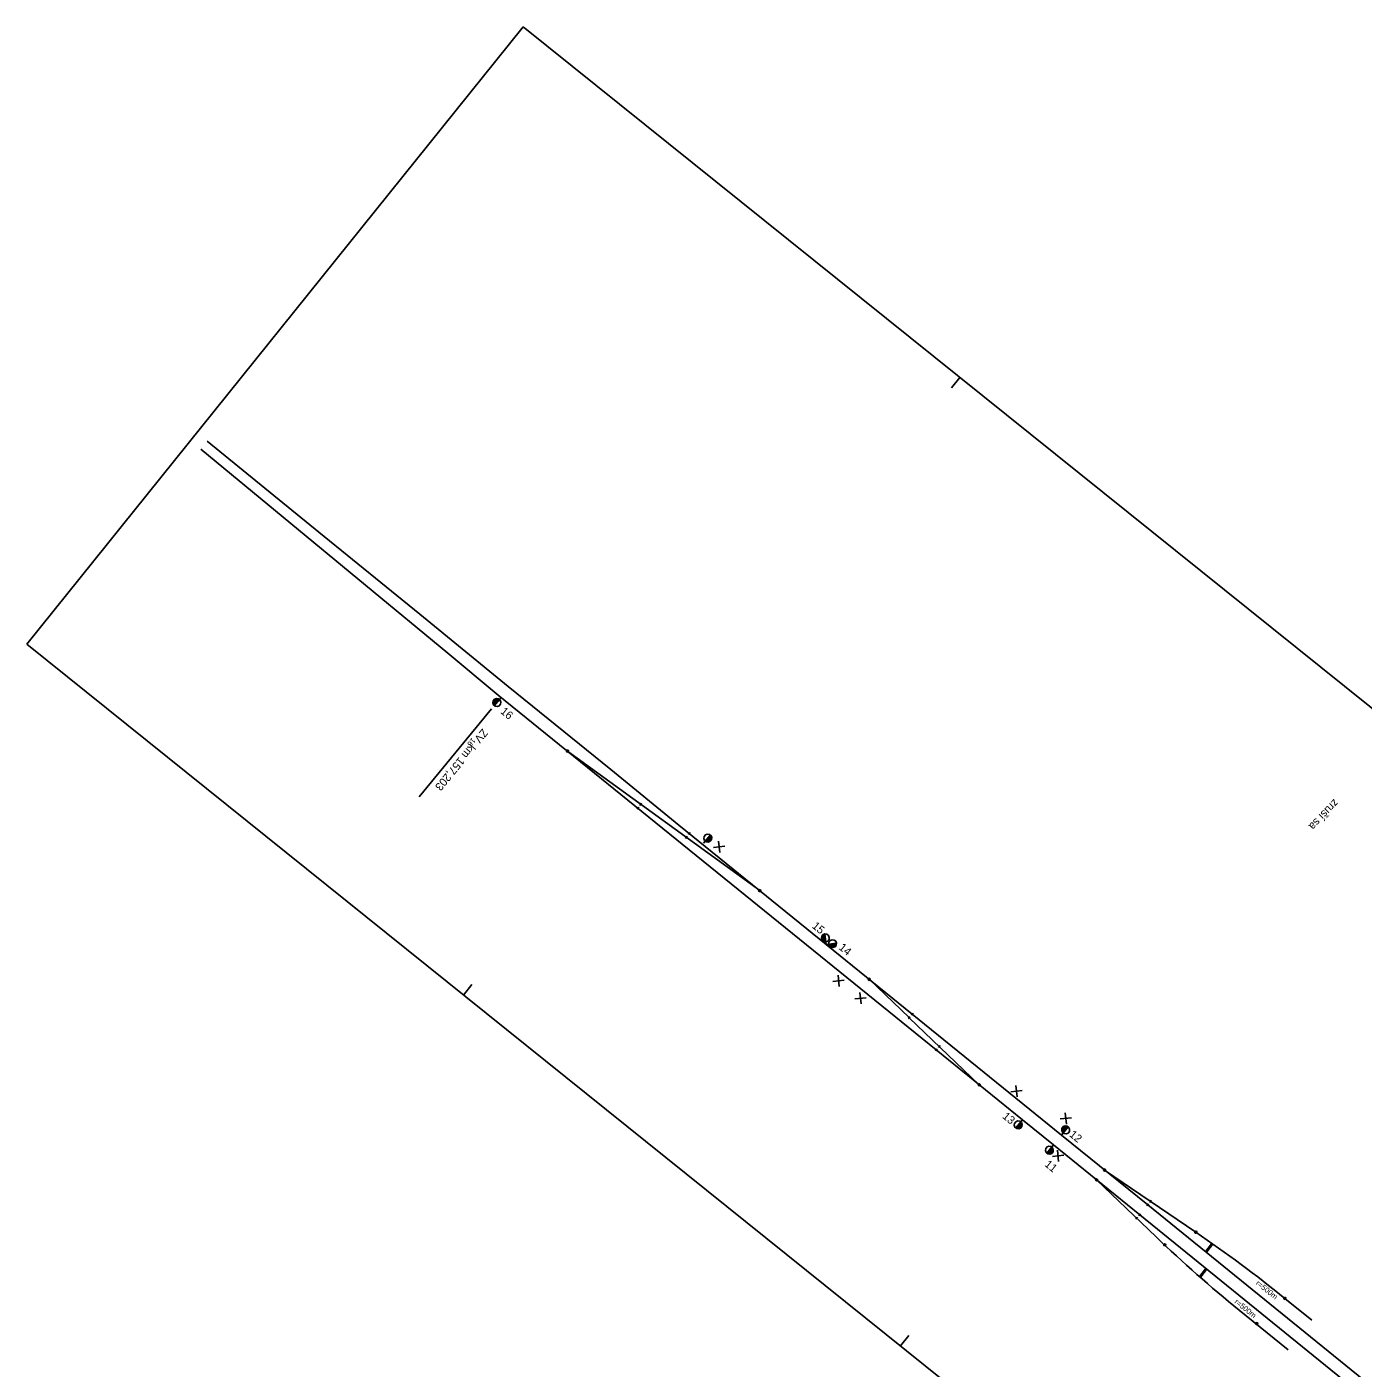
# Model space of a CAD drawing. Extents: x -486838 to -485015, y -1312876 to -1311330.
# Drawn here: x -486838 to -486337, y -1311833 to -1311330 of the extents above; entities that cross this region are included whole.
import ezdxf

# ---------------------------------------------------------------- set-up
doc = ezdxf.new("R2010")
doc.units = 0
for name, color, linetype in [('kolaj s', 7, 'Continuous'), ('Level 61', 7, 'Continuous'), ('popis 25', 7, 'Continuous'), ('popis 35', 7, 'Continuous'), ('stavby', 7, 'Continuous')]:
    doc.layers.add(name, color=color, linetype=linetype)

msp = doc.modelspace()

# ---------------------------------------------------------------- linework, layer by layer
at = {"layer": 'kolaj s'}
for p, q in [((-486770.47, -1311484.97), (-486728.55, -1311519.09)), ((-486680.25, -1311564.37), (-486772.84, -1311487.92)), ((-486728.55, -1311519.09), (-486690.72, -1311549.81)), ((-486690.72, -1311549.81), (-486657.65, -1311576.88)), ((-486661.35, -1311580.12), (-486680.25, -1311564.37)), ((-486657.65, -1311576.88), (-486619.12, -1311608)), ((-486661.35, -1311580.12), (-486497.17, -1311713.19)), ((-486635.41, -1311601.14), (-486635.41, -1311601.14)), ((-486635.41, -1311601.14), (-486563.34, -1311653.44)), ((-486619.12, -1311608), (-486593.64, -1311628.92)), ((-486609.3, -1311622.93), (-486608.68, -1311622.15)), ((-486608.99, -1311622.54), (-486608.99, -1311622.54)), ((-486608.22, -1311621.5), (-486607.59, -1311620.72)), ((-486607.91, -1311621.11), (-486607.91, -1311621.11)), ((-486593.64, -1311628.92), (-486538.46, -1311673.61)), ((-486590.04, -1311632.43), (-486589.41, -1311631.65)), ((-486589.72, -1311632.04), (-486589.72, -1311632.04)), ((-486584.38, -1311635.67), (-486581.89, -1311632.6)), ((-486591.18, -1311633.86), (-486590.55, -1311633.08)), ((-486590.87, -1311633.47), (-486590.87, -1311633.47)), ((-486584.38, -1311635.67), (-486584.38, -1311635.67)), ((-486563.34, -1311653.44), (-486563.34, -1311653.44)), ((-486538.46, -1311673.61), (-486506.15, -1311699.8)), ((-486522.3, -1311686.7), (-486522.3, -1311686.7)), ((-486522.3, -1311686.7), (-486507.29, -1311701.09)), ((-486506.94, -1311700.73), (-486507.64, -1311701.46)), ((-486507.29, -1311701.09), (-486507.29, -1311701.09)), ((-486481.02, -1311726.28), (-486507.29, -1311701.1)), ((-486505.83, -1311699.41), (-486506.46, -1311700.19)), ((-486506.15, -1311699.8), (-486506.15, -1311699.8)), ((-486506.15, -1311699.8), (-486450.22, -1311745.13)), ((-486497.49, -1311713.57), (-486496.86, -1311712.8)), ((-486464.86, -1311739.38), (-486497.17, -1311713.19)), ((-486497.17, -1311713.19), (-486497.17, -1311713.19)), ((-486496.38, -1311712.25), (-486495.68, -1311711.53)), ((-486496.03, -1311711.89), (-486496.03, -1311711.89)), ((-486481.02, -1311726.28), (-486481.02, -1311726.28)), ((-486464.86, -1311739.38), (-486453.21, -1311748.82)), ((-486450.22, -1311745.13), (-486417.9, -1311771.32)), ((-486453.21, -1311748.82), (-486420.89, -1311775.01)), ((-486434.06, -1311758.23), (-486434.06, -1311758.23)), ((-486434.06, -1311758.23), (-486399.86, -1311781.52)), ((-486437.05, -1311761.92), (-486437.05, -1311761.92)), ((-486437.05, -1311761.92), (-486414.73, -1311783.31)), ((-486417.59, -1311770.93), (-486418.22, -1311771.71)), ((-486417.9, -1311771.32), (-486114.2, -1312017.47)), ((-486417.9, -1311771.32), (-486417.9, -1311771.32)), ((-486416.59, -1311769.52), (-486417.15, -1311770.35)), ((-486416.87, -1311769.93), (-486416.87, -1311769.93)), ((-486421.69, -1311775.94), (-486422.38, -1311776.67)), ((-486422.04, -1311776.31), (-486422.04, -1311776.31)), ((-486420.58, -1311774.62), (-486421.21, -1311775.4)), ((-486420.89, -1311775.01), (-486117.19, -1312021.16)), ((-486420.89, -1311775.01), (-486420.89, -1311775.01)), ((-486399.86, -1311781.52), (-486399.86, -1311781.52)), ((-486411.54, -1311786.26), (-486411.54, -1311786.26)), ((-486366.48, -1311806.35), (-486366.48, -1311806.35)), ((-486366.48, -1311806.35), (-486356.38, -1311814.54)), ((-486383.59, -1311810.77), (-486365.28, -1311825.61)), ((-486377.05, -1311815.79), (-486377.05, -1311815.79))]:
    msp.add_line(p, q, dxfattribs=at)
for points in [[(-486635.16, -1311600.83), (-486635.02, -1311601.2), (-486635.27, -1311601.51), (-486635.66, -1311601.46), (-486635.81, -1311601.08), (-486635.56, -1311600.77), (-486635.16, -1311600.83)], [(-486581.59, -1311632.86), (-486582.21, -1311632.36), (-486582.97, -1311632.24), (-486583.69, -1311632.52), (-486584.19, -1311633.14), (-486584.3, -1311633.89), (-486584, -1311634.64), (-486583.42, -1311635.11), (-486582.65, -1311635.23), (-486581.93, -1311634.96), (-486581.43, -1311634.34), (-486581.32, -1311633.58), (-486581.59, -1311632.86), (-486581.55, -1311633.21), (-486581.94, -1311632.9), (-486582.13, -1311633.13), (-486581.47, -1311633.66), (-486581.5, -1311634.03), (-486582.32, -1311633.37), (-486582.5, -1311633.6), (-486581.61, -1311634.32), (-486581.8, -1311634.55), (-486582.7, -1311633.83), (-486582.88, -1311634.07), (-486581.99, -1311634.79), (-486582.29, -1311634.93), (-486583.07, -1311634.3), (-486583.26, -1311634.53), (-486582.6, -1311635.06), (-486583.1, -1311635.05), (-486583.45, -1311634.76)], [(-486563.09, -1311653.13), (-486562.95, -1311653.5), (-486563.2, -1311653.81), (-486563.59, -1311653.75), (-486563.74, -1311653.38), (-486563.49, -1311653.07), (-486563.09, -1311653.13)], [(-486521.99, -1311686.96), (-486522.37, -1311687.1), (-486522.68, -1311686.85), (-486522.61, -1311686.45), (-486522.24, -1311686.31), (-486521.93, -1311686.56), (-486521.99, -1311686.96)], [(-486481.33, -1311726.03), (-486480.96, -1311725.89), (-486480.65, -1311726.14), (-486480.71, -1311726.53), (-486481.08, -1311726.67), (-486481.39, -1311726.42), (-486481.33, -1311726.03)], [(-486433.75, -1311758.48), (-486434.12, -1311758.62), (-486434.43, -1311758.37), (-486434.37, -1311757.97), (-486434, -1311757.83), (-486433.69, -1311758.08), (-486433.75, -1311758.48)], [(-486436.74, -1311762.17), (-486437.11, -1311762.31), (-486437.42, -1311762.06), (-486437.36, -1311761.66), (-486436.99, -1311761.52), (-486436.68, -1311761.77), (-486436.74, -1311762.17)], [(-486399.64, -1311781.19), (-486399.47, -1311781.55), (-486399.69, -1311781.88), (-486400.09, -1311781.85), (-486400.26, -1311781.49), (-486400.04, -1311781.16), (-486399.64, -1311781.19)], [(-486411.26, -1311785.97), (-486411.15, -1311786.35), (-486411.42, -1311786.64), (-486411.81, -1311786.55), (-486411.92, -1311786.16), (-486411.65, -1311785.87), (-486411.26, -1311785.97)], [(-486366.73, -1311806.66), (-486366.87, -1311806.29), (-486366.62, -1311805.98), (-486366.23, -1311806.04), (-486366.08, -1311806.42), (-486366.33, -1311806.73), (-486366.73, -1311806.66)], [(-486377.3, -1311816.1), (-486377.44, -1311815.73), (-486377.19, -1311815.42), (-486376.79, -1311815.48), (-486376.65, -1311815.86), (-486376.9, -1311816.17), (-486377.3, -1311816.1)]]:
    msp.add_lwpolyline(points, dxfattribs=at)
for centre, start, end in [((-486068.73, -1311422.36), 226.2117, 230.9705), ((-486681.33, -1312194.77), 50.9712, 55.7405)]:
    msp.add_arc(centre, 500, start, end, dxfattribs=at)
at = {"layer": 'Level 61'}
for p, q in [((-486652.04, -1311329.55), (-486838.03, -1311561.1)), ((-486652.04, -1311329.55), (-486160.87, -1311724.08)), ((-486488.32, -1311461.06), (-486491.45, -1311464.96)), ((-486346.87, -1311955.63), (-486838.03, -1311561.1)), ((-486671.18, -1311688.71), (-486674.31, -1311692.61)), ((-486507.46, -1311820.22), (-486510.59, -1311824.12))]:
    msp.add_line(p, q, dxfattribs=at)
at = {"layer": 'popis 25'}
for p, q in [((-486396.13, -1311788.65), (-486393.94, -1311785.91)), ((-486395.77, -1311788.93), (-486393.59, -1311786.2)), ((-486398.39, -1311797.98), (-486396.2, -1311795.25)), ((-486398.03, -1311798.27), (-486395.85, -1311795.53))]:
    msp.add_line(p, q, dxfattribs=at)
at = {"layer": 'popis 35'}
for p, q in [((-486660.29, -1311580.98), (-486662.77, -1311584.06)), ((-486660.29, -1311580.98), (-486660.29, -1311580.98)), ((-486663.84, -1311585.3), (-486690.93, -1311618.31)), ((-486576.39, -1311636.82), (-486580.64, -1311637.28)), ((-486578.28, -1311639.18), (-486578.74, -1311634.93)), ((-486538.46, -1311673.61), (-486538.46, -1311673.61)), ((-486531.62, -1311687.05), (-486535.87, -1311687.52)), ((-486533.51, -1311689.41), (-486533.97, -1311685.16)), ((-486525.35, -1311695.96), (-486525.82, -1311691.71)), ((-486523.46, -1311693.61), (-486527.71, -1311694.07)), ((-486464.95, -1311728.41), (-486469.2, -1311728.87)), ((-486466.85, -1311730.77), (-486467.31, -1311726.52)), ((-486446.44, -1311738.62), (-486450.69, -1311739.08)), ((-486448.34, -1311740.97), (-486448.8, -1311736.72)), ((-486464.86, -1311739.38), (-486467.33, -1311742.46)), ((-486464.86, -1311739.38), (-486464.86, -1311739.38)), ((-486450.22, -1311745.13), (-486447.74, -1311742.05)), ((-486450.22, -1311745.13), (-486450.22, -1311745.13)), ((-486453.21, -1311748.82), (-486455.68, -1311751.9)), ((-486449.39, -1311752.65), (-486453.64, -1311753.12)), ((-486453.21, -1311748.82), (-486453.21, -1311748.82)), ((-486451.29, -1311755.01), (-486451.75, -1311750.76))]:
    msp.add_line(p, q, dxfattribs=at)
for points in [[(-486663.08, -1311583.81), (-486662.45, -1311584.31), (-486661.7, -1311584.42), (-486660.98, -1311584.15), (-486660.48, -1311583.52), (-486660.37, -1311582.77), (-486660.64, -1311582.05), (-486661.26, -1311581.55), (-486662.02, -1311581.44), (-486662.74, -1311581.71), (-486663.24, -1311582.33), (-486663.35, -1311583.09), (-486663.08, -1311583.81), (-486663.12, -1311583.46), (-486662.73, -1311583.77), (-486662.54, -1311583.54), (-486663.2, -1311583), (-486663.13, -1311582.68), (-486662.35, -1311583.3), (-486662.16, -1311583.07), (-486663.06, -1311582.35), (-486662.87, -1311582.11), (-486661.98, -1311582.83), (-486661.79, -1311582.6), (-486662.68, -1311581.88), (-486662.38, -1311581.74), (-486661.6, -1311582.37), (-486661.41, -1311582.13), (-486662.07, -1311581.6), (-486661.57, -1311581.62), (-486661.22, -1311581.9)], [(-486538.57, -1311672.64), (-486537.84, -1311672.36), (-486537.36, -1311671.75), (-486537.24, -1311670.99), (-486537.52, -1311670.26), (-486538.12, -1311669.78), (-486538.89, -1311669.66), (-486539.61, -1311669.94), (-486540.1, -1311670.54), (-486540.22, -1311671.31), (-486539.94, -1311672.03), (-486539.33, -1311672.52), (-486538.57, -1311672.64), (-486538.75, -1311672.29), (-486539.38, -1311672.36), (-486539.69, -1311672.11), (-486538.85, -1311672.01), (-486538.85, -1311671.69), (-486539.86, -1311671.84), (-486540, -1311671.54), (-486538.88, -1311671.41), (-486538.91, -1311671.13), (-486540.07, -1311671.22), (-486540.03, -1311670.93), (-486538.91, -1311670.81), (-486538.94, -1311670.53), (-486539.92, -1311670.64), (-486539.71, -1311670.3), (-486539.01, -1311670.22), (-486539.01, -1311669.9), (-486539.36, -1311669.94)], [(-486538.89, -1311669.67), (-486538.46, -1311673.61), (-486534.52, -1311673.18)], [(-486534.51, -1311673.18), (-486534.79, -1311672.45), (-486535.39, -1311671.97), (-486536.21, -1311671.85), (-486536.89, -1311672.13), (-486537.37, -1311672.74), (-486537.49, -1311673.5), (-486537.21, -1311674.23), (-486536.6, -1311674.71), (-486535.88, -1311674.84), (-486535.11, -1311674.55), (-486534.63, -1311673.94), (-486534.51, -1311673.18), (-486534.82, -1311673.39), (-486534.77, -1311673.88), (-486535.05, -1311674.23), (-486535.13, -1311673.46), (-486535.41, -1311673.49), (-486535.31, -1311674.47), (-486535.61, -1311674.61), (-486535.73, -1311673.49), (-486536.05, -1311673.56), (-486535.89, -1311674.64), (-486536.21, -1311674.64), (-486536.33, -1311673.59), (-486536.61, -1311673.62), (-486536.5, -1311674.6), (-486536.85, -1311674.32), (-486536.93, -1311673.62), (-486537.21, -1311673.65), (-486537.16, -1311674.07)], [(-486467.02, -1311742.71), (-486467.65, -1311742.2), (-486467.92, -1311741.46), (-486467.8, -1311740.72), (-486467.31, -1311740.12), (-486466.59, -1311739.83), (-486465.83, -1311739.94), (-486465.21, -1311740.44), (-486464.94, -1311741.16), (-486465.05, -1311741.92), (-486465.55, -1311742.54), (-486466.26, -1311742.82), (-486467.02, -1311742.71), (-486466.67, -1311742.67), (-486467.06, -1311742.35), (-486466.87, -1311742.12), (-486466.21, -1311742.65), (-486465.87, -1311742.54), (-486466.69, -1311741.89), (-486466.5, -1311741.65), (-486465.6, -1311742.37), (-486465.41, -1311742.14), (-486466.31, -1311741.42), (-486466.12, -1311741.18), (-486465.23, -1311741.91), (-486465.15, -1311741.58), (-486465.93, -1311740.95), (-486465.75, -1311740.72), (-486465.08, -1311741.25), (-486465.17, -1311740.8), (-486465.56, -1311740.48)], [(-486448.06, -1311741.8), (-486447.43, -1311742.3), (-486447.16, -1311743.05), (-486447.28, -1311743.79), (-486447.76, -1311744.39), (-486448.49, -1311744.67), (-486449.25, -1311744.56), (-486449.87, -1311744.06), (-486450.14, -1311743.34), (-486450.03, -1311742.59), (-486449.53, -1311741.96), (-486448.81, -1311741.69), (-486448.06, -1311741.8), (-486448.41, -1311741.84), (-486448.02, -1311742.15), (-486448.2, -1311742.39), (-486448.87, -1311741.85), (-486449.21, -1311741.96), (-486448.39, -1311742.62), (-486448.58, -1311742.85), (-486449.48, -1311742.13), (-486449.66, -1311742.37), (-486448.77, -1311743.09), (-486448.96, -1311743.32), (-486449.85, -1311742.6), (-486449.92, -1311742.93), (-486449.14, -1311743.56), (-486449.33, -1311743.79), (-486449.99, -1311743.26), (-486449.91, -1311743.71), (-486449.52, -1311744.02)], [(-486455.37, -1311752.15), (-486455.99, -1311751.65), (-486456.27, -1311750.91), (-486456.15, -1311750.17), (-486455.65, -1311749.55), (-486454.94, -1311749.28), (-486454.18, -1311749.39), (-486453.55, -1311749.89), (-486453.28, -1311750.61), (-486453.4, -1311751.37), (-486453.89, -1311751.98), (-486454.61, -1311752.26), (-486455.37, -1311752.15), (-486455.02, -1311752.11), (-486455.41, -1311751.8), (-486455.22, -1311751.57), (-486454.56, -1311752.1), (-486454.25, -1311751.96), (-486455.03, -1311751.33), (-486454.84, -1311751.1), (-486453.95, -1311751.82), (-486453.76, -1311751.58), (-486454.66, -1311750.86), (-486454.47, -1311750.63), (-486453.57, -1311751.35), (-486453.5, -1311751.02), (-486454.28, -1311750.4), (-486454.09, -1311750.16), (-486453.47, -1311750.66), (-486453.55, -1311750.21), (-486453.91, -1311749.93)]]:
    msp.add_lwpolyline(points, dxfattribs=at)

# ---------------------------------------------------------------- texts
at = {"layer": 'popis 25'}
for p in [(-486377.54, -1311800.98), (-486385.56, -1311807.97)]:
    msp.add_text('r=500m', height=2, rotation=321.2268, dxfattribs=at).set_placement(p)
at = {"layer": 'popis 35'}
for s, height, rotation, p in [('16', 3, 320.6268, (-486660.76, -1311586.67)), ('ZV  km 157,203', 3, 230.6268, (-486667.25, -1311592.52)), ('16', 2, 230.6268, (-486671.17, -1311595.99)), ('15', 3, 320.6268, (-486543.98, -1311667.13)), ('14', 3, 320.6268, (-486533.93, -1311675.2)), ('13', 3, 320.6268, (-486472.61, -1311738.49)), ('12', 3, 320.6268, (-486447.54, -1311745.34)), ('11', 3, 320.6268, (-486456.8, -1311756.49))]:
    msp.add_text(s, height=height, rotation=rotation, dxfattribs=at).set_placement(p)
at = {"layer": 'stavby'}
msp.add_text('zruší sa', height=3, rotation=226.2268, dxfattribs=at).set_placement((-486348.07, -1311618.94))

doc.saveas('drawing.dxf')
